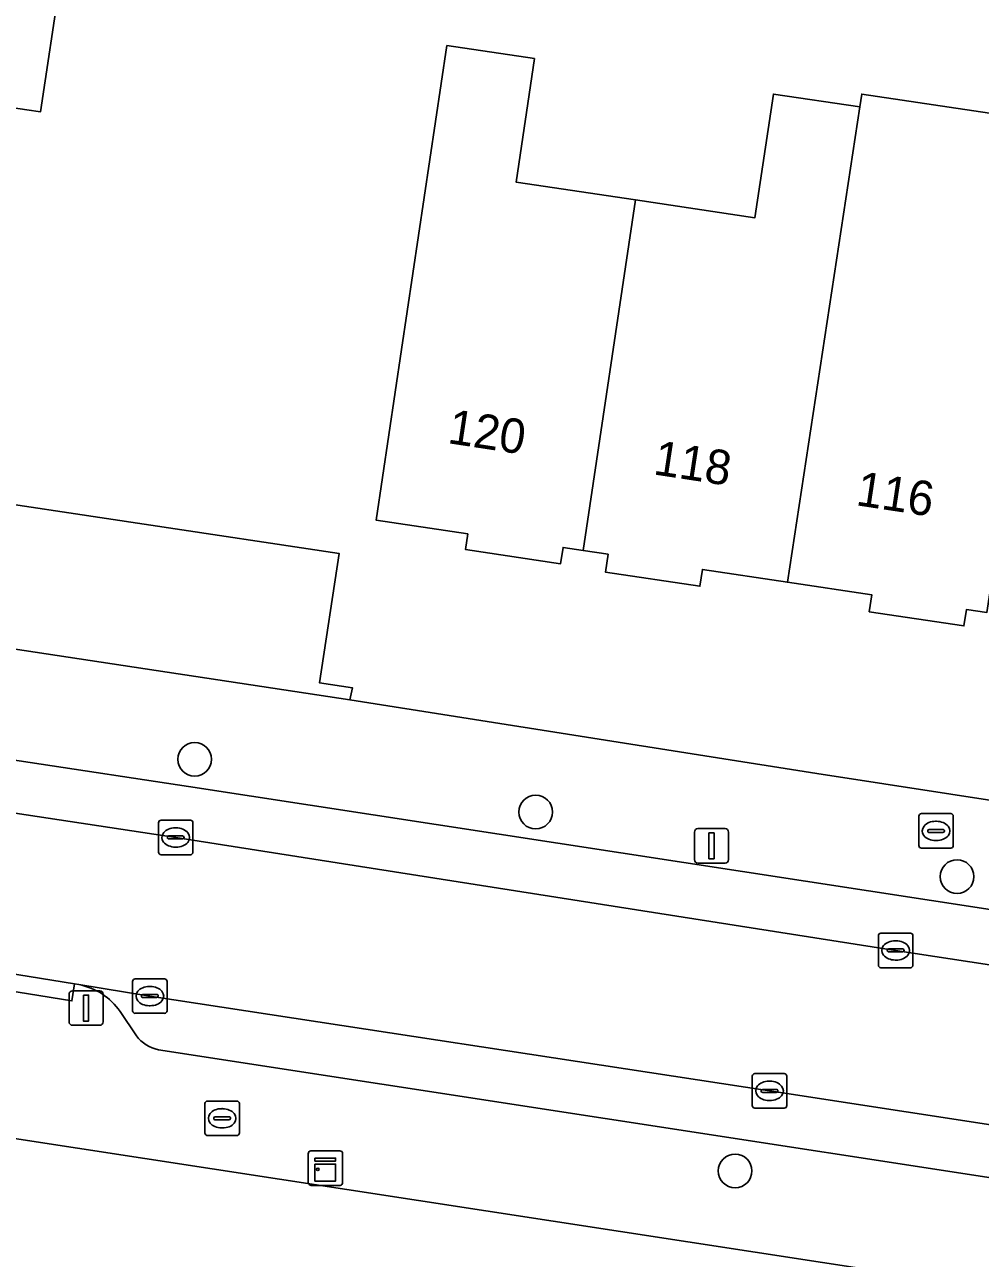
# Model space of a CAD drawing. Extents: x 161483 to 162250, y 379484 to 380833.
# Drawn here: x 161701.83 to 161729.55, y 380569.33 to 380605.11 of the extents above; entities that cross this region are included whole.
import ezdxf

# ---------------------------------------------------------------- set-up
doc = ezdxf.new("R2010")
doc.units = 0
for name, color, linetype in [('IMGEO_Boom', 7, 'Continuous'), ('IMGEO_Brandkraan', 7, 'Continuous'), ('IMGEO_Erf', 7, 'Continuous'), ('IMGEO_Kast', 7, 'Continuous'), ('IMGEO_Kolk', 7, 'Continuous'), ('IMGEO_Lichtmast', 7, 'Continuous'), ('IMGEO_Pand', 7, 'Continuous'), ('IMGEO_Pand_nummerreeks', 7, 'Continuous'), ('IMGEO_Parkeervlak_open', 7, 'Continuous'), ('IMGEO_Rijbaan_lokaal_open', 7, 'Continuous'), ('IMGEO_Voetpad_open', 7, 'Continuous')]:
    doc.layers.add(name, color=color, linetype=linetype)

msp = doc.modelspace()

# ---------------------------------------------------------------- linework, layer by layer
at = {"layer": 'IMGEO_Boom'}
for centre in [(161706.758, 380583.801), (161716.651, 380582.272), (161728.873, 380580.399), (161722.435, 380571.863)]:
    msp.add_circle(centre, 0.489, dxfattribs=at)
at = {"layer": 'IMGEO_Brandkraan'}
for p, q in [((161727.762, 380581.299), (161727.762, 380582.151)), ((161727.837, 380582.225), (161728.689, 380582.225)), ((161728.763, 380582.151), (161728.763, 380581.299)), ((161728.021, 380581.719), (161728.021, 380581.731)), ((161728.064, 380581.768), (161728.462, 380581.768)), ((161728.25, 380582.005), (161728.275, 380582.005)), ((161728.505, 380581.731), (161728.505, 380581.719)), ((161728.459, 380581.682), (161728.061, 380581.682)), ((161728.273, 380581.445), (161728.248, 380581.445)), ((161728.689, 380581.225), (161727.837, 380581.225)), ((161707.13, 380573.889), (161707.982, 380573.889)), ((161707.055, 380572.963), (161707.055, 380573.815)), ((161707.543, 380573.669), (161707.568, 380573.669)), ((161708.056, 380573.815), (161708.056, 380572.963)), ((161707.314, 380573.383), (161707.314, 380573.395)), ((161707.752, 380573.346), (161707.354, 380573.346)), ((161707.357, 380573.432), (161707.755, 380573.432)), ((161707.798, 380573.395), (161707.798, 380573.383)), ((161707.982, 380572.889), (161707.13, 380572.889)), ((161707.566, 380573.109), (161707.541, 380573.109))]:
    msp.add_line(p, q, dxfattribs=at)
for points in [[(161727.762, 380581.299), (161727.762, 380582.151)], [(161727.837, 380582.225), (161728.689, 380582.225)], [(161728.763, 380582.151), (161728.763, 380581.299)], [(161728.689, 380581.225), (161727.837, 380581.225)], [(161707.13, 380573.889), (161707.982, 380573.889)], [(161707.055, 380572.963), (161707.055, 380573.815)], [(161708.056, 380573.815), (161708.056, 380572.963)], [(161707.982, 380572.889), (161707.13, 380572.889)]]:
    msp.add_lwpolyline(points, dxfattribs=at)
for centre, radius, start, end in [((161727.839, 380582.149), 0.0765, 91.552, 178.448), ((161727.839, 380582.149), 0.0765, 91.552, 178.448), ((161728.687, 380582.149), 0.0765, 1.552, 88.448), ((161728.687, 380582.149), 0.0765, 1.552, 88.448), ((161728.061, 380581.728), 0.0403, 85.8775, 175.7526), ((161728.058, 380581.718), 0.0366, 178.938, 274.7102), ((161728.462, 380581.725), 0.043, 264.8664, 352.4533), ((161728.466, 380581.73), 0.0386, 1.7309, 96.639), ((161727.839, 380581.301), 0.0765, 181.552, 268.448), ((161727.839, 380581.301), 0.0765, 181.552, 268.448), ((161728.687, 380581.301), 0.0765, 271.552, 358.448), ((161728.687, 380581.301), 0.0765, 271.552, 358.448), ((161707.132, 380573.813), 0.0765, 91.552, 178.448), ((161707.132, 380573.813), 0.0765, 91.552, 178.448), ((161707.98, 380573.813), 0.0765, 1.552, 88.448), ((161707.98, 380573.813), 0.0765, 1.552, 88.448), ((161707.354, 380573.392), 0.0403, 85.8775, 175.7526), ((161707.351, 380573.382), 0.0366, 178.938, 274.7102), ((161707.755, 380573.389), 0.043, 264.8664, 352.4533), ((161707.759, 380573.394), 0.0386, 1.7309, 96.639), ((161707.132, 380572.965), 0.0765, 181.552, 268.448), ((161707.132, 380572.965), 0.0765, 181.552, 268.448), ((161707.98, 380572.965), 0.0765, 271.552, 358.448), ((161707.98, 380572.965), 0.0765, 271.552, 358.448)]:
    msp.add_arc(centre, radius, start, end, dxfattribs=at)
for centre, major_axis, ratio, start_param, end_param in [((161728.249, 380581.725), (-0.387, 0.002), 0.722429, 4.712389, 7.853982), ((161728.274, 380581.725), (-0.39, 0.002), 0.717154, 1.570796, 4.712389), ((161707.542, 380573.389), (-0.387, 0.002), 0.722429, 4.712389, 7.853982), ((161707.567, 380573.389), (-0.39, 0.002), 0.717154, 1.570796, 4.712389)]:
    msp.add_ellipse(centre, major_axis=major_axis, ratio=ratio, start_param=start_param, end_param=end_param, dxfattribs=at)
at = {"layer": 'IMGEO_Erf'}
for points in [[(161684.141, 380632.376), (161683.425, 380627.743), (161680.38, 380605.802), (161680.26, 380605.833), (161679.923, 380603.696), (161679.803, 380603.707), (161679.209, 380599.887), (161687.051, 380598.715), (161687.633, 380602.612), (161692.578, 380601.873), (161693.597, 380601.721), (161691.87, 380590.21), (161699.267, 380589.1), (161699.623, 380591.473), (161710.946, 380589.774), (161710.382, 380586.016), (161711.341, 380585.872), (161711.262, 380585.528), (161724.808, 380583.386), (161754.33, 380578.833)], [(161699.718, 380628.991), (161703.687, 380628.398), (161703.038, 380624.059), (161704.543, 380623.834), (161704.389, 380622.805), (161703.216, 380614.962), (161701.954, 380606.517), (161702.852, 380606.383), (161702.283, 380602.576), (161701.887, 380602.635), (161696.942, 380603.375)], [(161729.733, 380588.055), (161729.143, 380588.143), (161729.072, 380587.669), (161726.325, 380588.079), (161726.399, 380588.573), (161723.951, 380588.939), (161721.487, 380589.307), (161721.415, 380588.823), (161718.674, 380589.233), (161718.751, 380589.75), (161718.025, 380589.859), (161717.444, 380589.946), (161717.374, 380589.474), (161714.61, 380589.887), (161714.678, 380590.34), (161712.018, 380590.738), (161712.757, 380595.684), (161714.076, 380604.503), (161716.615, 380604.124), (161716.079, 380600.544), (161719.544, 380600.026), (161723.01, 380599.508), (161723.546, 380603.095), (161726.052, 380602.721), (161726.109, 380603.096), (161731.896, 380602.231)], [(161746.578, 380565.893), (161701.408, 380572.822), (161675.834, 380576.755), (161672.785, 380556.708), (161672.018, 380551.67), (161669.47, 380534.918), (161668.107, 380525.958), (161665.107, 380506.236), (161664.729, 380506.368), (161663.777, 380500), (161663.405, 380497.51), (161661.323, 380483.575), (161659.867, 380473.831), (161659.847, 380473.707), (161657.766, 380460.798), (161657.736, 380460.494), (161657.919, 380460.405), (161659.307, 380459.731), (161660.495, 380459.537), (161723.59, 380449.899)]]:
    msp.add_lwpolyline(points, dxfattribs=at)
at = {"layer": 'IMGEO_Kast'}
for p, q in [((161710.126, 380572.445), (161710.967, 380572.445)), ((161710.967, 380572.445), (161710.126, 380572.445)), ((161710.051, 380571.52), (161710.051, 380572.361)), ((161710.051, 380572.361), (161710.051, 380571.52)), ((161711.051, 380572.37), (161711.051, 380571.529)), ((161711.051, 380571.529), (161711.051, 380572.37)), ((161710.976, 380571.445), (161710.135, 380571.445)), ((161710.135, 380571.445), (161710.976, 380571.445))]:
    msp.add_line(p, q, dxfattribs=at)
for points in [[(161710.246, 380572.235), (161710.846, 380572.235), (161710.846, 380572.15), (161710.246, 380572.15), (161710.246, 380572.235)], [(161710.246, 380572.06), (161710.846, 380572.06), (161710.846, 380571.571), (161710.246, 380571.571), (161710.246, 380572.06)]]:
    msp.add_lwpolyline(points, dxfattribs=at)
msp.add_circle((161710.33, 380571.909), 0.0377, dxfattribs=at)
for centre, start, end in [((161710.129, 380572.367), 92.4484, 184.2845), ((161710.129, 380572.367), 92.4484, 184.2845), ((161710.973, 380572.367), 2.4484, 94.2845), ((161710.973, 380572.367), 2.4484, 94.2845), ((161710.129, 380571.523), 182.4484, 274.2845), ((161710.129, 380571.523), 182.4484, 274.2845), ((161710.973, 380571.523), 272.4484, 4.2845), ((161710.973, 380571.523), 272.4484, 4.2845)]:
    msp.add_arc(centre, 0.0779, start, end, dxfattribs=at)
at = {"layer": 'IMGEO_Kolk'}
for p, q in [((161705.707, 380581.109), (161705.707, 380581.961)), ((161705.782, 380582.035), (161706.634, 380582.035)), ((161706.195, 380581.815), (161706.22, 380581.815)), ((161706.708, 380581.961), (161706.708, 380581.109)), ((161705.966, 380581.529), (161705.966, 380581.541)), ((161706.404, 380581.492), (161706.006, 380581.492)), ((161706.009, 380581.578), (161706.407, 380581.578)), ((161706.45, 380581.541), (161706.45, 380581.529)), ((161706.634, 380581.035), (161705.782, 380581.035)), ((161706.218, 380581.255), (161706.193, 380581.255)), ((161726.591, 380577.832), (161726.591, 380578.684)), ((161726.666, 380578.758), (161727.518, 380578.758)), ((161727.079, 380578.538), (161727.104, 380578.538)), ((161727.592, 380578.684), (161727.592, 380577.832)), ((161726.85, 380578.252), (161726.85, 380578.264)), ((161727.288, 380578.215), (161726.89, 380578.215)), ((161726.893, 380578.301), (161727.291, 380578.301)), ((161727.334, 380578.264), (161727.334, 380578.252)), ((161727.102, 380577.978), (161727.077, 380577.978)), ((161705.032, 380577.434), (161705.884, 380577.434)), ((161727.518, 380577.758), (161726.666, 380577.758)), ((161704.957, 380576.508), (161704.957, 380577.36)), ((161705.445, 380577.214), (161705.47, 380577.214)), ((161705.958, 380577.36), (161705.958, 380576.508)), ((161705.216, 380576.928), (161705.216, 380576.94)), ((161705.654, 380576.891), (161705.256, 380576.891)), ((161705.259, 380576.977), (161705.657, 380576.977)), ((161705.7, 380576.94), (161705.7, 380576.928)), ((161705.884, 380576.434), (161705.032, 380576.434)), ((161705.468, 380576.654), (161705.443, 380576.654)), ((161722.932, 380573.759), (161722.932, 380574.611)), ((161723.007, 380574.685), (161723.859, 380574.685)), ((161723.933, 380574.611), (161723.933, 380573.759)), ((161723.191, 380574.179), (161723.191, 380574.191)), ((161723.234, 380574.228), (161723.632, 380574.228)), ((161723.42, 380574.465), (161723.445, 380574.465)), ((161723.675, 380574.191), (161723.675, 380574.179)), ((161723.629, 380574.142), (161723.231, 380574.142)), ((161723.443, 380573.905), (161723.418, 380573.905)), ((161723.859, 380573.685), (161723.007, 380573.685))]:
    msp.add_line(p, q, dxfattribs=at)
for points in [[(161705.707, 380581.109), (161705.707, 380581.961)], [(161705.782, 380582.035), (161706.634, 380582.035)], [(161706.708, 380581.961), (161706.708, 380581.109)], [(161706.634, 380581.035), (161705.782, 380581.035)], [(161726.591, 380577.832), (161726.591, 380578.684)], [(161726.666, 380578.758), (161727.518, 380578.758)], [(161727.592, 380578.684), (161727.592, 380577.832)], [(161705.032, 380577.434), (161705.884, 380577.434)], [(161727.518, 380577.758), (161726.666, 380577.758)], [(161704.957, 380576.508), (161704.957, 380577.36)], [(161705.958, 380577.36), (161705.958, 380576.508)], [(161705.884, 380576.434), (161705.032, 380576.434)], [(161722.932, 380573.759), (161722.932, 380574.611)], [(161723.007, 380574.685), (161723.859, 380574.685)], [(161723.933, 380574.611), (161723.933, 380573.759)], [(161723.859, 380573.685), (161723.007, 380573.685)]]:
    msp.add_lwpolyline(points, dxfattribs=at)
for centre, radius, start, end in [((161705.784, 380581.959), 0.0765, 91.552, 178.448), ((161705.784, 380581.959), 0.0765, 91.552, 178.448), ((161706.632, 380581.959), 0.0765, 1.552, 88.448), ((161706.632, 380581.959), 0.0765, 1.552, 88.448), ((161706.006, 380581.538), 0.0403, 85.8775, 175.7526), ((161706.003, 380581.528), 0.0366, 178.938, 274.7102), ((161706.407, 380581.535), 0.043, 264.8664, 352.4533), ((161706.411, 380581.54), 0.0386, 1.7309, 96.639), ((161705.784, 380581.111), 0.0765, 181.552, 268.448), ((161705.784, 380581.111), 0.0765, 181.552, 268.448), ((161706.632, 380581.111), 0.0765, 271.552, 358.448), ((161706.632, 380581.111), 0.0765, 271.552, 358.448), ((161726.668, 380578.682), 0.0765, 91.552, 178.448), ((161726.668, 380578.682), 0.0765, 91.552, 178.448), ((161727.516, 380578.682), 0.0765, 1.552, 88.448), ((161727.516, 380578.682), 0.0765, 1.552, 88.448), ((161726.89, 380578.261), 0.0403, 85.8775, 175.7526), ((161726.887, 380578.251), 0.0366, 178.938, 274.7102), ((161727.291, 380578.258), 0.043, 264.8664, 352.4533), ((161727.295, 380578.263), 0.0386, 1.7309, 96.639), ((161726.668, 380577.834), 0.0765, 181.552, 268.448), ((161726.668, 380577.834), 0.0765, 181.552, 268.448), ((161727.516, 380577.834), 0.0765, 271.552, 358.448), ((161727.516, 380577.834), 0.0765, 271.552, 358.448), ((161705.034, 380577.358), 0.0765, 91.552, 178.448), ((161705.034, 380577.358), 0.0765, 91.552, 178.448), ((161705.882, 380577.358), 0.0765, 1.552, 88.448), ((161705.882, 380577.358), 0.0765, 1.552, 88.448), ((161705.256, 380576.937), 0.0403, 85.8775, 175.7526), ((161705.253, 380576.927), 0.0366, 178.938, 274.7102), ((161705.657, 380576.934), 0.043, 264.8664, 352.4533), ((161705.661, 380576.939), 0.0386, 1.7309, 96.639), ((161705.034, 380576.51), 0.0765, 181.552, 268.448), ((161705.034, 380576.51), 0.0765, 181.552, 268.448), ((161705.882, 380576.51), 0.0765, 271.552, 358.448), ((161705.882, 380576.51), 0.0765, 271.552, 358.448), ((161723.009, 380574.609), 0.0765, 91.552, 178.448), ((161723.009, 380574.609), 0.0765, 91.552, 178.448), ((161723.857, 380574.609), 0.0765, 1.552, 88.448), ((161723.857, 380574.609), 0.0765, 1.552, 88.448), ((161723.231, 380574.188), 0.0403, 85.8775, 175.7526), ((161723.636, 380574.19), 0.0386, 1.7309, 96.639), ((161723.228, 380574.178), 0.0366, 178.938, 274.7102), ((161723.632, 380574.185), 0.043, 264.8664, 352.4533), ((161723.009, 380573.761), 0.0765, 181.552, 268.448), ((161723.009, 380573.761), 0.0765, 181.552, 268.448), ((161723.857, 380573.761), 0.0765, 271.552, 358.448), ((161723.857, 380573.761), 0.0765, 271.552, 358.448)]:
    msp.add_arc(centre, radius, start, end, dxfattribs=at)
for centre, major_axis, ratio, start_param, end_param in [((161706.194, 380581.535), (-0.387, 0.002), 0.722429, 4.712389, 7.853982), ((161706.219, 380581.535), (-0.39, 0.002), 0.717154, 1.570796, 4.712389), ((161727.078, 380578.258), (-0.387, 0.002), 0.722429, 4.712389, 7.853982), ((161727.103, 380578.258), (-0.39, 0.002), 0.717154, 1.570796, 4.712389), ((161705.444, 380576.934), (-0.387, 0.002), 0.722429, 4.712389, 7.853982), ((161705.469, 380576.934), (-0.39, 0.002), 0.717154, 1.570796, 4.712389), ((161723.419, 380574.185), (-0.387, 0.002), 0.722429, 4.712389, 7.853982), ((161723.444, 380574.185), (-0.39, 0.002), 0.717154, 1.570796, 4.712389)]:
    msp.add_ellipse(centre, major_axis=major_axis, ratio=ratio, start_param=start_param, end_param=end_param, dxfattribs=at)
at = {"layer": 'IMGEO_Lichtmast'}
for p, q in [((161721.354, 380581.791), (161722.144, 380581.791)), ((161722.144, 380581.791), (161721.354, 380581.791)), ((161721.254, 380580.891), (161721.254, 380581.691)), ((161721.254, 380581.691), (161721.254, 380580.891)), ((161722.244, 380581.691), (161722.244, 380580.891)), ((161722.244, 380580.891), (161722.244, 380581.691)), ((161722.144, 380580.791), (161721.354, 380580.791)), ((161721.354, 380580.791), (161722.144, 380580.791)), ((161703.213, 380577.086), (161704.003, 380577.086)), ((161704.003, 380577.086), (161703.213, 380577.086)), ((161703.113, 380576.186), (161703.113, 380576.986)), ((161703.113, 380576.986), (161703.113, 380576.186)), ((161704.103, 380576.986), (161704.103, 380576.186)), ((161704.103, 380576.186), (161704.103, 380576.986)), ((161704.003, 380576.086), (161703.213, 380576.086)), ((161703.213, 380576.086), (161704.003, 380576.086))]:
    msp.add_line(p, q, dxfattribs=at)
for points in [[(161721.674, 380581.666), (161721.824, 380581.666), (161721.824, 380580.916), (161721.674, 380580.916), (161721.674, 380581.666)], [(161703.533, 380576.961), (161703.683, 380576.961), (161703.683, 380576.211), (161703.533, 380576.211), (161703.533, 380576.961)]]:
    msp.add_lwpolyline(points, dxfattribs=at)
for centre, start, end in [((161721.354, 380581.691), 90, 180), ((161721.354, 380581.691), 90, 180), ((161722.144, 380581.691), 0, 90), ((161722.144, 380581.691), 360, 90), ((161721.354, 380580.891), 180, 270), ((161721.354, 380580.891), 180, 270), ((161722.144, 380580.891), 270, 0), ((161722.144, 380580.891), 270, 0), ((161703.213, 380576.986), 90, 180), ((161703.213, 380576.986), 90, 180), ((161704.003, 380576.986), 0, 90), ((161704.003, 380576.986), 360, 90), ((161703.213, 380576.186), 180, 270), ((161703.213, 380576.186), 180, 270), ((161704.003, 380576.186), 270, 0), ((161704.003, 380576.186), 270, 0)]:
    msp.add_arc(centre, 0.1, start, end, dxfattribs=at)
at = {"layer": 'IMGEO_Pand'}
for points in [[(161703.216, 380614.962), (161697.597, 380615.849), (161688.336, 380617.311), (161687.614, 380612.476), (161686.663, 380612.618), (161686.281, 380610.06), (161687.125, 380609.934), (161687.013, 380609.186), (161697.574, 380607.607), (161696.942, 380603.375), (161701.887, 380602.635), (161702.283, 380602.576), (161702.852, 380606.383), (161701.954, 380606.517)], [(161718.025, 380589.859), (161719.544, 380600.026), (161716.079, 380600.544), (161716.615, 380604.124), (161714.076, 380604.503), (161712.757, 380595.684), (161712.018, 380590.738), (161714.678, 380590.34), (161714.61, 380589.887), (161717.374, 380589.474), (161717.444, 380589.946)], [(161723.951, 380588.939), (161726.052, 380602.721), (161723.546, 380603.095), (161723.01, 380599.508), (161719.544, 380600.026), (161718.025, 380589.859), (161718.751, 380589.75), (161718.674, 380589.233), (161721.415, 380588.823), (161721.487, 380589.307)], [(161731.292, 380598.274), (161731.896, 380602.231), (161726.109, 380603.096), (161726.052, 380602.721), (161723.951, 380588.939), (161726.399, 380588.573), (161726.325, 380588.079), (161729.072, 380587.669), (161729.143, 380588.143), (161729.733, 380588.055)]]:
    msp.add_lwpolyline(points, close=True, dxfattribs=at)
msp.add_lwpolyline([(161682.27, 380589.92), (161711.262, 380585.528), (161711.341, 380585.872), (161710.382, 380586.016), (161710.946, 380589.774), (161699.623, 380591.473)], dxfattribs=at)
at = {"layer": 'IMGEO_Parkeervlak_open'}
for points in [[(161751.383, 380576.136), (161706.575, 380583.016), (161683.607, 380586.497)], [(161680.794, 380585.397), (161684.371, 380584.84), (161706.209, 380581.535), (161727.091, 380578.257), (161745.481, 380575.457), (161748.16, 380575.062), (161753.997, 380574.189)], [(161747.528, 380570.507), (161743.383, 380571.123), (161723.434, 380574.186), (161705.458, 380576.935), (161703.396, 380577.269)], [(161704.594, 380576.489), (161705.068, 380575.783)], [(161705.711, 380575.377), (161744.456, 380569.416)]]:
    msp.add_lwpolyline(points, dxfattribs=at)
for centre, radius, start, end in [((161703.044, 380575.419), 1.883, 34.6294, 79.2355), ((161705.923, 380576.425), 1.069, 216.8949, 258.5673)]:
    msp.add_arc(centre, radius, start, end, dxfattribs=at)
at = {"layer": 'IMGEO_Rijbaan_lokaal_open'}
msp.add_lwpolyline([(161706.209, 380581.535), (161684.371, 380584.84), (161680.794, 380585.397), (161680.527, 380585.439), (161679.524, 380585.486), (161678.919, 380580.973), (161679.587, 380580.882), (161683.501, 380580.347), (161693.523, 380578.834), (161697.21, 380578.268), (161697.341, 380578.247), (161703.276, 380577.288), (161703.396, 380577.269), (161705.458, 380576.935), (161723.434, 380574.186), (161743.383, 380571.123), (161747.528, 380570.507), (161748.16, 380575.062), (161745.481, 380575.457), (161727.091, 380578.257)], close=True, dxfattribs=at)
at = {"layer": 'IMGEO_Voetpad_open'}
for points in [[(161711.262, 380585.528), (161682.27, 380589.92), (161677.021, 380590.715), (161676.592, 380588.066), (161676.589, 380588.037), (161676.323, 380586.395)], [(161683.607, 380586.497), (161706.575, 380583.016), (161751.383, 380576.136)], [(162007.859, 380539.593), (162001.608, 380540.698), (162000, 380540.965), (161989.926, 380542.639), (161963.411, 380546.705), (161933.1, 380551.357), (161926.533, 380552.341), (161923.744, 380552.759), (161920.738, 380553.21), (161887.994, 380558.235), (161850.616, 380563.993), (161845.302, 380564.812), (161842.113, 380565.304), (161840.43, 380565.564), (161785.522, 380574.037), (161759.686, 380578.007), (161759.209, 380578.08), (161755.449, 380578.66), (161754.33, 380578.833), (161724.808, 380583.386), (161711.262, 380585.528)], [(161676.405, 380581.019), (161675.834, 380576.755), (161701.408, 380572.822), (161746.578, 380565.893), (161752.702, 380564.649)], [(161703.396, 380577.269), (161703.276, 380577.288), (161703.196, 380576.793), (161697.261, 380577.755), (161697.341, 380578.247), (161697.21, 380578.268)], [(161705.068, 380575.783), (161704.594, 380576.489)], [(161744.456, 380569.416), (161705.711, 380575.377)]]:
    msp.add_lwpolyline(points, dxfattribs=at)
msp.add_lwpolyline([(161697.341, 380578.247), (161697.261, 380577.755), (161703.196, 380576.793), (161703.276, 380577.288)], close=True, dxfattribs=at)
for centre, radius, start, end in [((161703.044, 380575.419), 1.883, 34.6294, 79.2355), ((161705.923, 380576.425), 1.069, 216.8949, 258.5673)]:
    msp.add_arc(centre, radius, start, end, dxfattribs=at)

# ---------------------------------------------------------------- texts
at = {"layer": 'IMGEO_Pand_nummerreeks'}
for s, rotation, p in [('120', 351.3577, (161714.067, 380592.975)), ('118', 351.3577, (161720.035, 380592.069)), ('116', 351.3598, (161725.911, 380591.175))]:
    msp.add_text(s, height=1, rotation=rotation, dxfattribs=at).set_placement(p)

doc.saveas('drawing.dxf')
